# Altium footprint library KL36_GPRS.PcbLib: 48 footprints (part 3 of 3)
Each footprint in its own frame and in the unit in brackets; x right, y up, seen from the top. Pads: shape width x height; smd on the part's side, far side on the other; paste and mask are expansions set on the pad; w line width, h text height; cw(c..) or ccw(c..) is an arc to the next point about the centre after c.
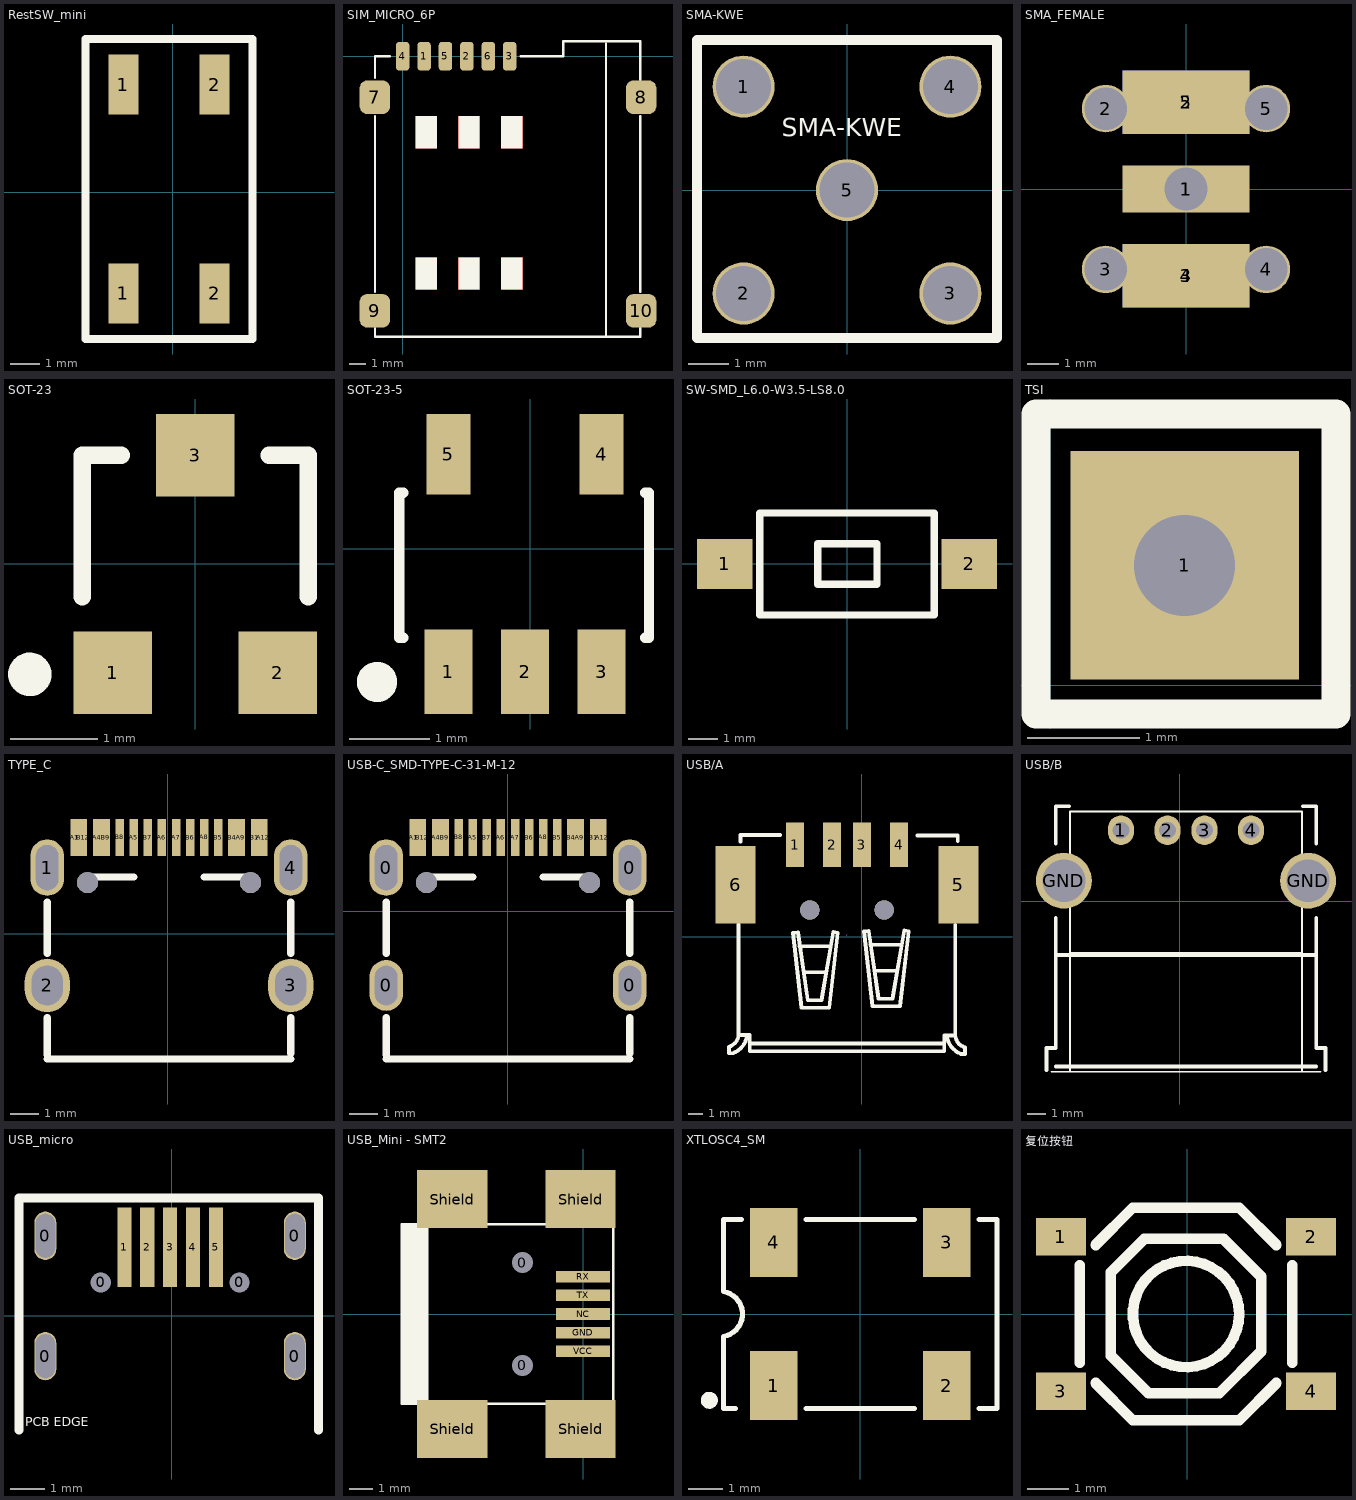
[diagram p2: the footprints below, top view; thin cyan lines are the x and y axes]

## RestSW_mini [mm]
pads (4):
  rect 1x2 smd: 1(-1.651,-3.378) 1(-1.651,3.607) 2(1.397,-3.378) 2(1.397,3.607)
Top Overlay:
  lines w0.254: -2.921,-4.902 2.667,-4.902 2.667,-3.29 2.667,5.131 -2.921,5.131 -2.921,-4.902

## SIM_MICRO_6P [mm]
pads (10):
  rrect50% 0.8x1.7 smd: 1(1.27,0) 2(3.81,0) 3(6.35,0) 4(0,0) 5(2.54,0) 6(5.08,0)
  rrect50% 1.8x2 smd: 7(-1.65,-2.425) 8(14.15,-2.425) 9(-1.65,-15.105) 10(14.15,-15.105)
Top Layer:
  pour cut-out: 3.302,-5.461 4.572,-5.461 4.572,-3.556 3.302,-3.556
  pour cut-out: 5.842,-13.843 7.112,-13.843 7.112,-11.938 5.842,-11.938
  pour cut-out: 3.302,-13.843 4.572,-13.843 4.572,-11.938 3.302,-11.938
  pour cut-out: 0.762,-13.843 2.032,-13.843 2.032,-11.938 0.762,-11.938
  pour cut-out: 5.842,-5.461 7.112,-5.461 7.112,-3.556 5.842,-3.556
  pour cut-out: 0.762,-5.461 2.032,-5.461 2.032,-3.556 0.762,-3.556
Top Overlay:
  rectangle: 5.842,-13.843 7.112,-11.938
  rectangle: 3.302,-13.843 4.572,-11.938
  rectangle: 0.762,-13.843 2.032,-11.938
  rectangle: 5.842,-5.461 7.112,-3.556
  rectangle: 3.302,-5.461 4.572,-3.556
  rectangle: 0.762,-5.461 2.032,-3.556
  lines w0.127: -1.651,-16.129 -1.651,-16.637 14.097,-16.637 14.097,-16.129 ; -1.651,-13.97 -1.651,-3.556 ; -1.651,-1.27 -1.651,0 -0.762,0 ; 6.985,0 9.525,0 9.525,0.889 14.097,0.889 14.097,-1.397 ; 12.065,-16.637 12.065,0.762 ; 14.097,-13.97 14.097,-3.556

## SMA-KWE [mil]
pads (5):
  round 60 hole 53.15: 1(-100,100) 2(-100,-100) 3(100,-100) 4(100,100) 5(0,0)
Top Overlay:
  lines w10: -145,-143 -145,145 145,145 145,-143 -145,-143
  text "SMA-KWE" at -63,46 h30

## SMA_FEMALE [mm]
pads (10):
  rect 4x1.5 smd: 1(0,0)
  round 1.5 hole 1.35: 1(0,0) 2(-2.54,2.54) 3(-2.54,-2.54) 4(2.54,-2.54) 5(2.54,2.54)
  rect 4x2 smd: 2(0,2.74) 3(0,-2.74)
  rect 4x2 smd far side: 4(0,-2.74) 5(0,2.74)

## SOT-23 [mm]
pads (3):
  rect 0.9x0.95 smd: 1(-0.95,-1.25) 2(0.95,-1.25) 3(0,1.25)
Top Overlay:
  circle w0.25: c-1.903,-1.27 r0.125
  lines w0.2: -1.3,-0.375 -1.3,1.25 -0.85,1.25 ; 0.85,1.25 1.3,1.25 1.3,-0.375

## SOT-23-5 [mm]
pads (5):
  rect 0.6x1.05 smd: 1(-1.016,-1.524) 2(-0.066,-1.524) 3(0.884,-1.524)
  rect 0.55x1 smd: 4(0.884,1.176) 5(-1.016,1.176)
Top Overlay:
  circle w0.25: c-1.903,-1.651 r0.125
  lines w0.127: -1.576,-1.103 -1.626,-1.103 -1.626,0.697 -1.576,0.697 ; 1.424,-1.103 1.474,-1.103 1.474,0.697 1.424,0.697
3D body: height 1.09, standoff -0.01, extent -1.502,-1.527 1.397,1.273

## SW-SMD_L6.0-W3.5-LS8.0 [mm] "轻触开关（贴片式，上按）"
pads (2):
  rect 1.9x1.7 smd: 1(-4.2,0) 2(4.2,0)
Top Overlay:
  lines w0.254: -3,-1.75 -3,1.75 3,1.75 3,-1.75 -3,-1.75 ; -1.001,-0.701 1.031,-0.701 1.031,0.701 -1.001,0.701 -1.001,-0.701

## TSI [mil]
pads (1):
  rect 80x80 hole 35.43: 1(47,42)
Top Overlay:
  lines w10: -5,-10 100,-10 100,95 -5,95 -5,-10

## TYPE_C [mm]
pads (22):
  oval 1.2x2 hole 0.8 slot 1.6 at 90 deg: 1(-4.269,2.343) 4(4.371,2.343)
  oval 1.6x1.9 hole 1.1 slot 1.4 at 90 deg: 2(-4.269,-1.837) 3(4.371,-1.837)
  rect 0.3x1.3 smd: A1(-3.299,3.411) A4(-2.499,3.411) A5(-1.199,3.411) A6(-0.199,3.411) A7(0.301,3.411) A8(1.3,3.412) A9(2.601,3.411) A12(3.401,3.411) B1(3.101,3.411) B4(2.301,3.411) B5(1.801,3.411) B6(0.801,3.411) B7(-0.699,3.411) B8(-1.699,3.412) B9(-2.199,3.411) B12(-2.999,3.411)
  round 0.75 hole 0.75 unplated: ""(-2.839,1.813) ""(2.941,1.813)
Top Overlay:
  lines w0.254: -4.269,-4.439 4.371,-4.439 ; -4.269,-4.304 -4.269,-2.968 ; -4.269,-0.706 -4.269,1.112 ; -2.949,2.008 -1.199,2.008 ; 1.298,2.011 3.048,2.011 ; 4.371,-4.253 4.371,-2.968 ; 4.371,-0.706 4.371,1.112

## USB-C_SMD-TYPE-C-31-M-12 [mm]
pads (22):
  oval 1.2x1.8 hole 0.8 slot 1.4 at 90 deg: 0(-4.32,-2.624) 0(4.32,-2.624)
  oval 1.2x2 hole 0.8 slot 1.6 at 90 deg: 0(-4.32,1.556) 0(4.32,1.556)
  rect 0.3x1.3 smd: A1(-3.35,2.623) A4(-2.55,2.623) A5(-1.25,2.623) A6(-0.25,2.623) A7(0.25,2.623) A8(1.25,2.624) A9(2.55,2.623) A12(3.35,2.623) B1(3.05,2.623) B4(2.25,2.623) B5(1.75,2.623) B6(0.75,2.623) B7(-0.75,2.623) B8(-1.75,2.624) B9(-2.25,2.623) B12(-3.05,2.623)
  round 0.75 hole 0.75 unplated: ""(-2.89,1.026) ""(2.89,1.026)
Top Overlay:
  lines w0.254: -4.32,-5.227 4.32,-5.227 ; -4.32,-5.091 -4.32,-3.755 ; -4.32,-1.493 -4.32,0.325 ; -3,1.221 -1.25,1.221 ; 1.247,1.224 2.997,1.224 ; 4.32,-5.04 4.32,-3.755 ; 4.32,-1.493 4.32,0.325

## USB/A [mm]
pads (8):
  rect 1.2x3 smd: 1(-4.5,6.198) 2(-2.005,6.198) 3(-0.005,6.198) 4(2.5,6.198)
  rect 2.7x5.2 smd: 5(6.495,3.498) 6(-8.505,3.498)
  round 1.3 hole 1.3 unplated: ""(-3.505,1.798) ""(1.495,1.798)
Top Overlay:
  lines w0.254: -8.961,-7.41 ccw(c-9.209,-6.527) -8.295,-6.605 ; -8.96,-7.411 -8.96,-7.849 -8.676,-7.849 ; -8.676,-7.85 ccw(c-9.264,-6.402) -7.726,-6.679 ; -8.316,0.833 -8.316,-6.629 -7.559,-6.629 -7.559,-7.188 ; -8.178,6.413 -8.178,6.84 -5.516,6.84 ; -4.214,-0.648 -2.132,-0.648 ; -3.884,-2.4 -2.436,-2.4 ; 0.561,-0.546 2.644,-0.546 ; 0.891,-2.299 2.339,-2.299 ; 3.732,6.804 6.45,6.804 6.45,6.449 ; 5.548,-6.655 5.548,-7.188 ; 5.569,-6.655 6.284,-6.655 6.284,0.787 ; 5.716,-6.729 ccw(c7.253,-6.453) 6.666,-7.9 ; 6.285,-6.656 ccw(c7.199,-6.578) 6.95,-7.461 6.949,-7.899 6.665,-7.899 ; -7.559,-7.188 5.548,-7.188 ; -7.559,-7.188 -7.559,-7.722 5.522,-7.722 5.548,-7.696 5.548,-7.188 ; -4.642,0.259 -4.062,-4.788 -2.208,-4.788 -1.624,0.267 -1.928,0.318 -2.716,-4.28 -3.656,-4.28 -4.311,0.285 -4.642,0.259 ; 0.133,0.361 0.713,-4.686 2.567,-4.686 3.152,0.368 2.847,0.419 2.059,-4.178 1.12,-4.178 0.464,0.386 0.133,0.361
Mechanical 15:
  lines w0.003: -1.031,0.065 -0.98,0.116

## USB/B [mm]
pads (6):
  oval 1.4x1.6 hole 0.9: 1(-3.175,3.81) 2(-0.675,3.81) 3(1.325,3.81) 4(3.825,3.81)
  round 3 hole 2.3: GND(-6.245,1.1) GND(6.895,1.1)
Top Overlay:
  lines w0.1: -6.925,-9.18 7.575,-9.18 ; -5.925,-9.18 -5.925,4.81 6.575,4.81 6.575,-9.18 ; -5.925,-2.78 6.575,-2.78
  lines w0.2: -7.175,-9.1 -7.175,-7.9 -6.675,-7.9 -6.675,-0.9 ; -6.675,-8.9 7.325,-8.9 ; -6.675,-2.9 7.325,-2.9 ; -6.675,3.1 -6.675,5.1 -5.975,5.1 ; 6.625,5.1 7.325,5.1 7.325,3.1 ; 7.325,-0.9 7.325,-7.9 7.825,-7.9 7.825,-9.1

## USB_micro [mil]
pads (11):
  rrect100% 25x55 hole 22 slot 50 at 90 deg: 0(-144,-46) 0(-144,91) 0(140,-46) 0(140,91)
  round 22 hole 23 mask+0: 0(-81,38) 0(77,38)
  rect 16x90 smd mask+3: 1(-54,78) 2(-28,78) 3(-2,78) 4(24,78) 5(50,78)
Top Overlay:
  lines w10: -174,-130 -174,134 167,134 167,-130
  text "PCB EDGE" at -167,-130 h18

## USB_Mini - SMT2 [mm] "USB Mini Connector (F 1363522, Tyco/AMP 1734035-2)"
height 10.16
pads (11):
  round 0.8 hole 0.9: 0(-2.6,-2.2) 0(-2.6,2.2)
  rect 2.3x0.5 smd: GND(0,-0.8) NC(0,0) RX(0,1.6) TX(0,0.8) VCC(0,-1.6)
  rect 3x2.5 smd: Shield(-5.6,-4.925) Shield(-5.6,4.925) Shield(-0.1,-4.925) Shield(-0.1,4.925)
Top Overlay:
  rectangle: -7.825,-3.85 -6.625,3.85
  lines w0.1: -7.775,-3.85 1.3,-3.85 1.3,3.85 -7.775,3.85

## XTLOSC4_SM [mil]
pads (4):
  rect 55x80 smd: 1(-100,-83.07) 2(100,-83.07) 3(100,83.07) 4(-100,83.07)
Top Overlay:
  circle w9.84: c-174.92,-100 r4.92
  lines w6: -144.5,-109.5 -158.5,-109.5 -158.5,-26 ccw(c-162.86,0) -158.5,26 -158.5,109.5 -137.5,109.5 ; -62.5,-109.5 62.5,-109.5 ; -62.5,109.5 62.5,109.5 ; 137.5,-109.5 158.5,-109.5 158.5,109.5 137.5,109.5

## 复位按钮 [mil]
pads (4):
  rect 47.2x35.4 smd: 1(-119.4,73.2)
  rect 47.2x35.5 smd: 2(116.82,73.25) 3(-119.4,-72.45) 4(116.82,-72.45)
Top Overlay:
  circle w10: c-1.29,0.4 r50.2
  lines w10: -101.69,-45.6 -101.69,46.4 ; -86.73,-64.76 -51.49,-100 48.91,-100 84.15,-64.76 ; -86.73,65.56 -51.49,100.8 48.91,100.8 84.15,65.56 ; 99.11,-45.6 99.11,46.4 ; -72.19,-38.9 -36.69,-74.4 30.21,-74.4 69.61,-35 69.61,35.8 34.11,71.3 -40.69,71.3 -72.19,39.8 -72.19,-38.9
